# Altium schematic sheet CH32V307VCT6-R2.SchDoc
size A2
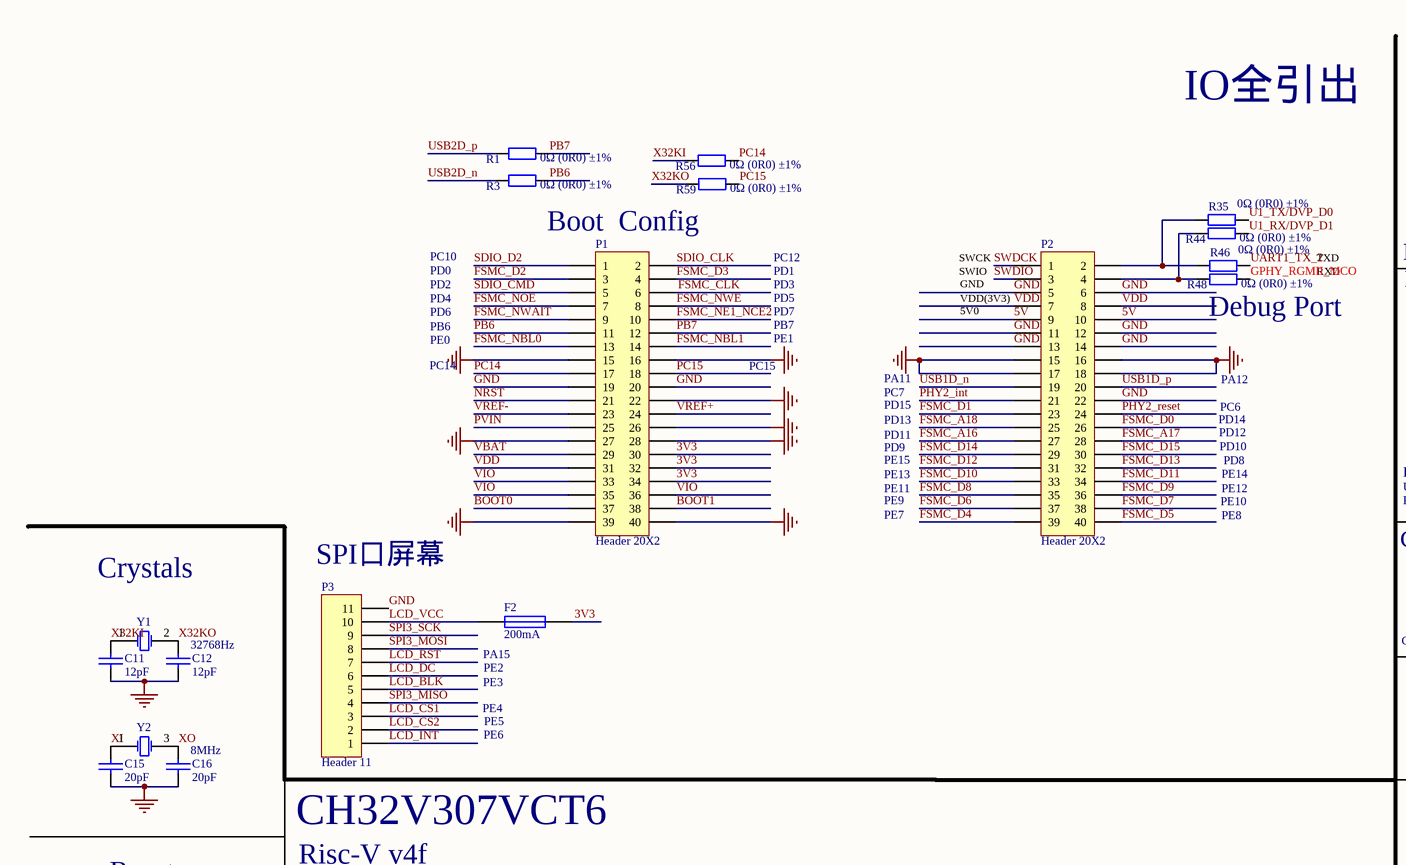
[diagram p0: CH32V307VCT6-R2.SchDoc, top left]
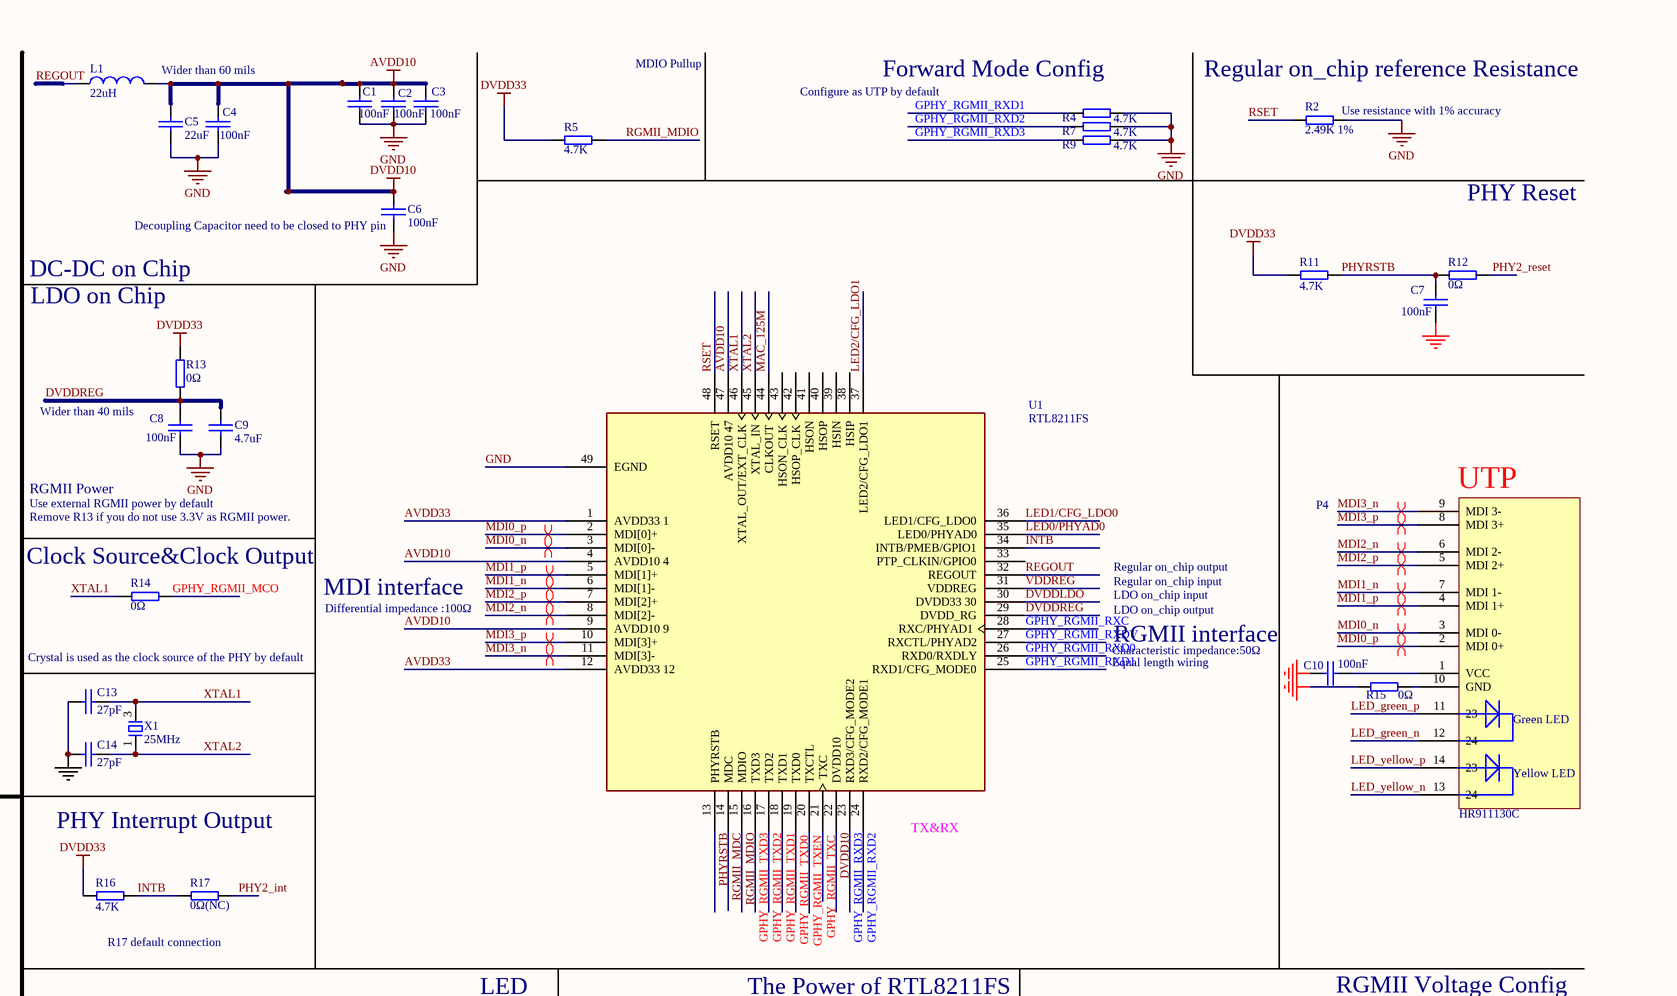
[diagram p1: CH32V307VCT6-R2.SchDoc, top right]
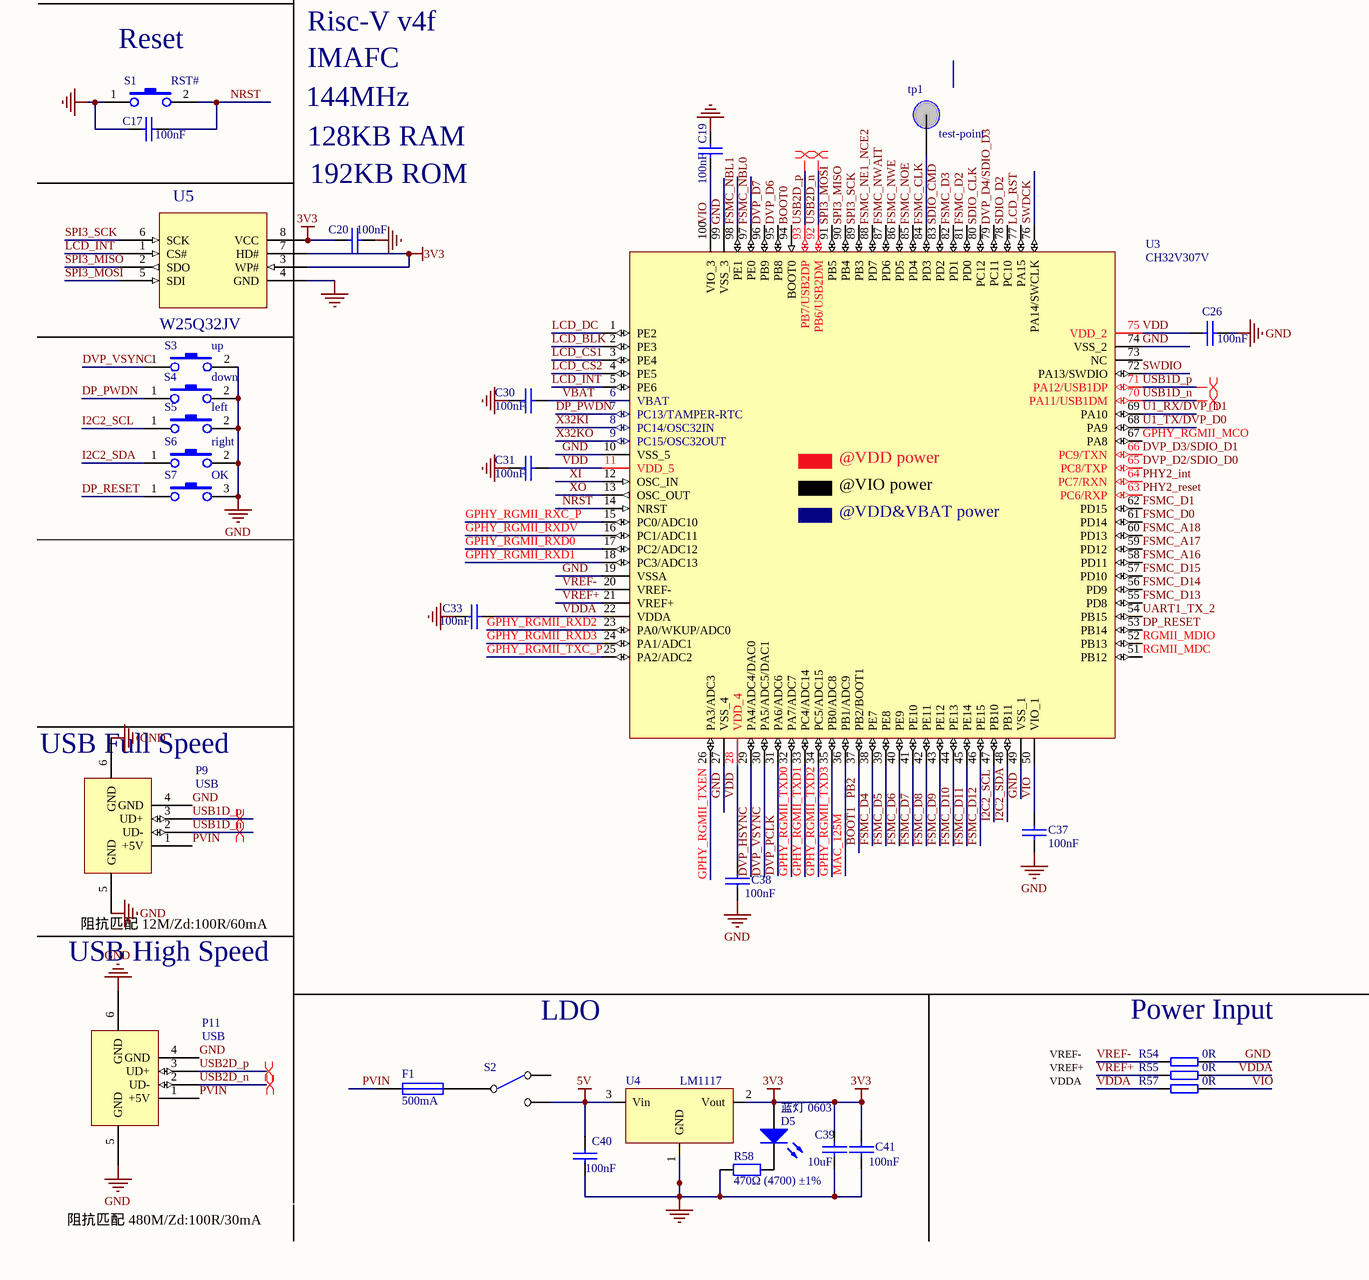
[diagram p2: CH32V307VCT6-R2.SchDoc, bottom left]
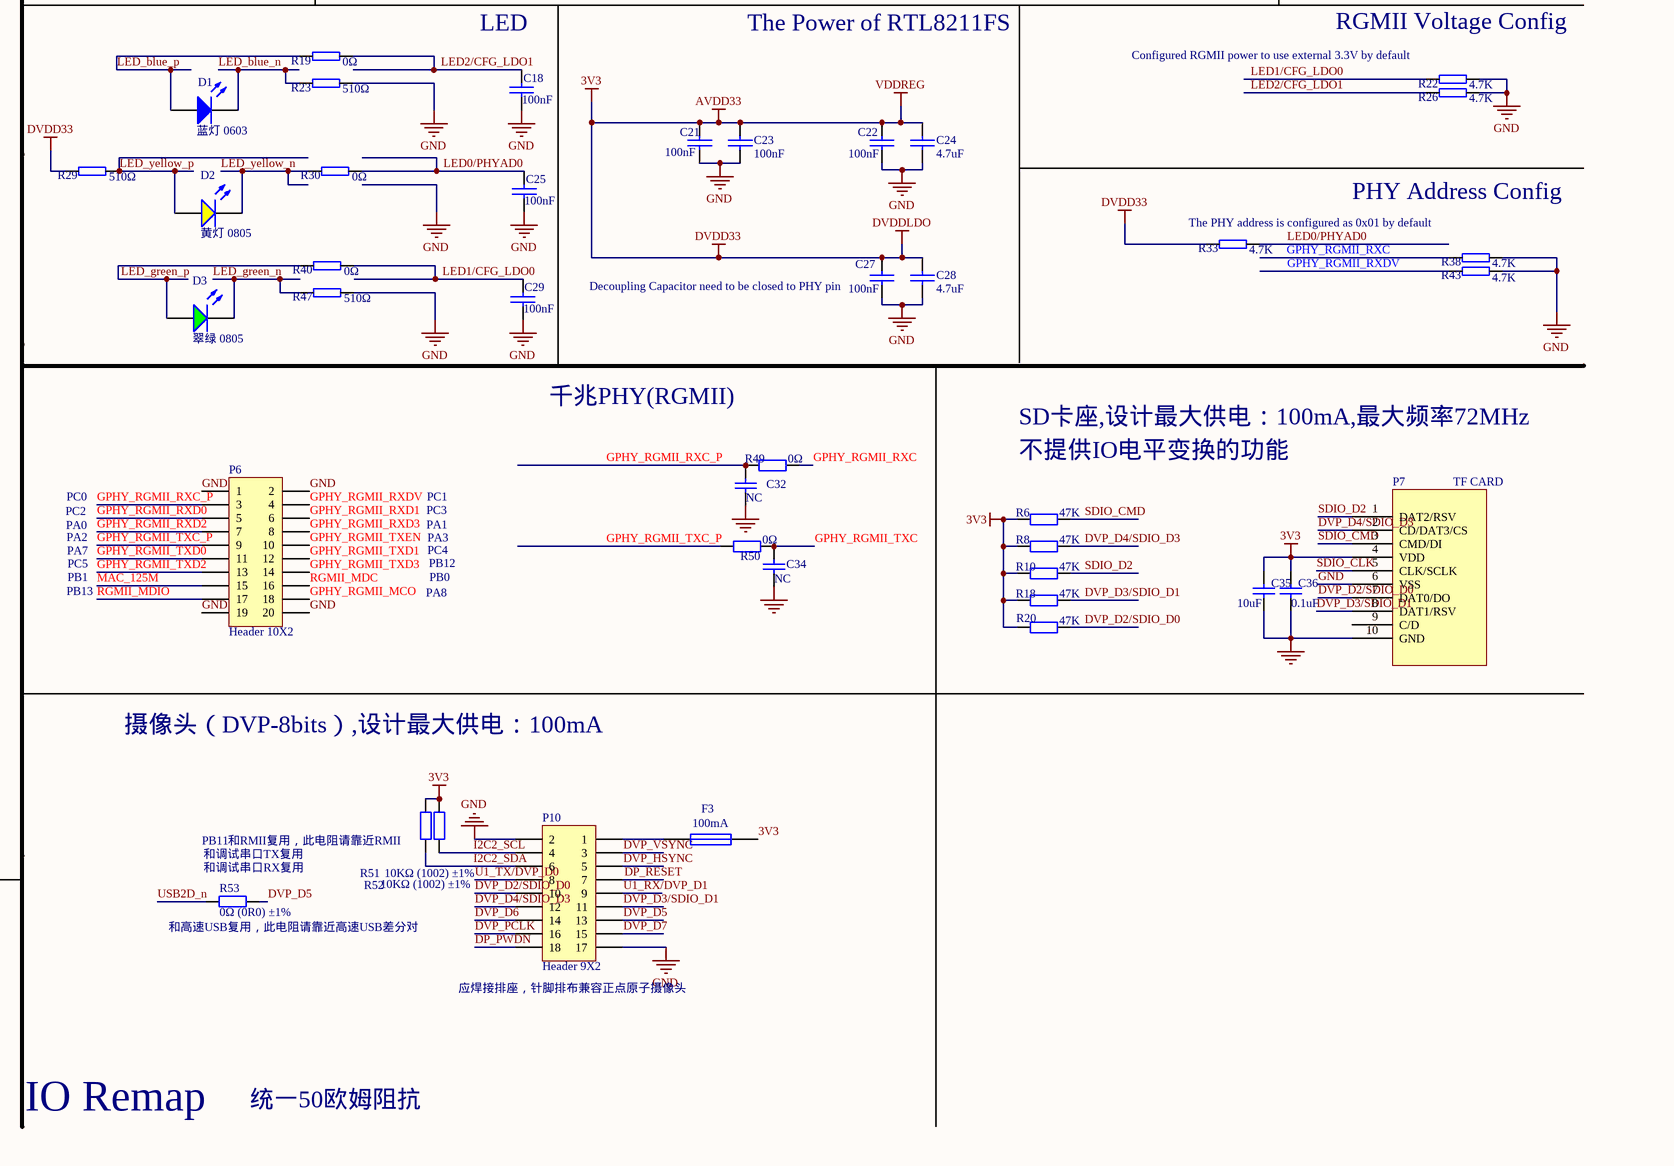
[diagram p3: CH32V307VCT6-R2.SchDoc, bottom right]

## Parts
C1  100nF  [0603_C]
C2  100nF  [0603_C]
C3  100nF  [0603_C]
C4  100nF  [0603_C]
C5  22uF  [0805_C]
C6  100nF  [0603_C]
C7  100nF  [0603_C]
C8  100nF  [0603_C]
C9  4.7uF  [0603_C]
C10  100nF  [0603_C]
C11  12pF  [0603_C]
C12  12pF  [0603_C]
C13  27pF  [0603_C]
C14  27pF  [0603_C]
C15  20pF  [0603_C]
C16  20pF  [0603_C]
C17  100nF  [0603_C]
C18  100nF  [0603_C]
C19  100nF  [0603_C]
C20  100nF  [0603_C]
C21  100nF  [0603_C]
C22  100nF  [0603_C]
C23  100nF  [0603_C]
C24  4.7uF  [0603_C]
C25  100nF  [0603_C]
C26  100nF  [0603_C]
C27  100nF  [0603_C]
C28  4.7uF  [0603_C]
C29  100nF  [0603_C]
C30  100nF  [0603_C]
C31  100nF  [0603_C]
C32  NC  [0402_C]
C33  100nF  [0603_C]
C34  NC  [0402_C]
C35  10uF  [0805_C]
C36  0.1uF  [0603_C]
C37  100nF  [0603_C]
C38  100nF  [0603_C]
C39  10uF  [0805_C]
C40  100nF  [0603_C]
C41  100nF  [0603_C]
D1  蓝灯 0603  [0603_LED_S1]
D2  黄灯 0805  [0603_LED_S1]
D3  翠绿 0805  [0603_LED_S1]
D5  蓝灯 0603  [0603_LED_S1]
F1  500mA  [0805]
F2  200mA  [0805]
F3  100mA  [0805]
L1  22uH  [0805]
P1  Header 20X2  [HDR2X20]
P2  Header 20X2  [HDR2X20]
P3  Header 11  [HDR1X11]
P4  HR911130C  [RJ45-1G]
P6  Header 10X2  [HDR2X10]
P7  TF CARD  [TF103]
P9  USB  [USBAF]
P10  Header 9X2  [HDR2X9]
P11  USB  [USBAF]
R1  0Ω (0R0) ±1%  [0402]
R2  2.49K 1%  [0603_R]
R3  0Ω (0R0) ±1%  [0402]
R4  4.7K  [0603_R]
R5  4.7K  [0603_R]
R6  47K  [0603_R]
R7  4.7K  [0603_R]
R8  47K  [0603_R]
R9  4.7K  [0603_R]
R10  47K  [0603_R]
R11  4.7K  [0603_R]
R12  0Ω  [0603_R]
R13  0Ω  [0603_R]
R14  0Ω  [0603_R]
R15  0Ω  [0603_R]
R16  4.7K  [0603_R]
R17  0Ω(NC)  [0603_R]
R18  47K  [0603_R]
R19  0Ω  [0603_R]
R20  47K  [0603_R]
R22  4.7K  [0603_R]
R23  510Ω  [0603_R]
R26  4.7K  [0603_R]
R29  510Ω  [0603_R]
R30  0Ω  [0603_R]
R33  4.7K  [0603_R]
R35  0Ω (0R0) ±1%  [0402_R]
R38  4.7K  [0603_R]
R40  0Ω  [0603_R]
R43  4.7K  [0603_R]
R44  0Ω (0R0) ±1%  [0402_R]
R46  0Ω (0R0) ±1%  [0402_R]
R47  510Ω  [0603_R]
R48  0Ω (0R0) ±1%  [0402_R]
R49  0Ω  [0402_R]
R50  0Ω  [0402_R]
R51  10KΩ (1002) ±1%  [0603_R]
R52  10KΩ (1002) ±1%  [0603_R]
R53  0Ω (0R0) ±1%  [0402]
R54  0R  [0402]
R55  0R  [0402]
R56  0Ω (0R0) ±1%  [0402]
R57  0R  [0402]
R58  470Ω (4700) ±1%  [0603_R]
R59  0Ω (0R0) ±1%  [0402]
S1  RST#  [SMD_6.1x3.65x2.5mm-KEY]
S2  SW SPDT  [Horizontal Slide Switch_8.7x4.4mm-2D]  (value not drawn)
S3  up  [SMD_6.1x3.65x2.5mm-KEY]
S4  down  [SMD_6.1x3.65x2.5mm-KEY]
S5  left  [SMD_6.1x3.65x2.5mm-KEY]
S6  right  [SMD_6.1x3.65x2.5mm-KEY]
S7  OK  [KEYD]
tp1  test-point  [POINT]
U1  RTL8211FS  [QFN-48_6x6x04P]
U3  CH32V307V  [LQFP100]
U4  LM1117  [SOT-223]
U5  W25Q32JV  [SOIC-8_208mil]
X1  25MHz  [SMD-3225_4P]
Y1  32768Hz  [FC-135]
Y2  8MHz  [SMD-3225_4P]

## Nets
3V3: C20.2 C21.2 C22.2 C23.2 C24.2 C27.2 C28.2 C35.2 C36.2 C39.1 C41.1 D5.A F2.2 F3.2 P1.30 P1.32 P1.34 P7.4(VDD) R5.1 R6.2 R8.2 R10.2 R11.2 R13.2 R16.2 R18.2 R20.2 R29.1 R33.1 R51.2 R52.2 U1.1(AVDD33_1) U1.12(AVDD33_12) U1.30(DVDD33_30) U1.31(VDDREG) U4.2(Vout) U5.3(WP#) U5.7(HD#) U5.8(VCC)  [also labelled AVDD33, DVDD33, DVDDLDO, VDDREG]
5V: C40.1 P2.9 P2.10 S2.2(NC) U4.3(Vin)
AVDD10: C1.2 C2.2 C3.2 C4.2 C5.2 C6.2 L1.2 U1.4(AVDD10_4) U1.9(AVDD10_9) U1.22(DVDD10) U1.47(AVDD10_47)  [also labelled DVDD10]
GND: C1.1 C2.1 C3.1 C4.1 C5.1 C6.1 C7.1 C8.1 C9.1 C10.2 C11.1 C12.1 C13.1 C14.1 C15.1 C16.1 C17.1 C18.2 C19.2 C20.1 C21.1 C22.1 C23.1 C24.1 C25.2 C26.1 C27.1 C28.1 C29.2 C30.1 C31.2 C32.1 C33.2 C34.1 C35.1 C36.1 C37.1 C38.1 C39.2 C40.2 C41.2 P1.15 P1.16 P1.19 P1.20 P1.22 P1.26 P1.27 P1.28 P1.39 P1.40 P2.5 P2.6 P2.11 P2.12 P2.13 P2.14 P2.15 P2.16 P2.17 P2.18 P2.22 P3.11 P6.1 P6.2 P6.19 P6.20 P7.6(VSS) P7.10(GND) P9.4(GND) P9.5(GND) P9.6(GND) P10.2 P10.17 P11.4(GND) P11.5(GND) P11.6(GND) R2.2 R4.2 R7.2 R9.2 R15.2 R22.2 R23.2 R26.2 R38.2 R43.2 R47.2 R54.1 R58.1 S1.1 S3.2 S4.2 S5.2 S6.2 S7.3 U1.49(EGND) U3.10(VSS_5) U3.19(VSSA) U3.27(VSS_4) U3.49(VSS_1) U3.74(VSS_2) U3.99(VSS_3) U4.1(GND) U5.4(GND)
BOOT0: P1.37 U3.94(BOOT0)
BOOT1: P1.38 U3.37(PB2/BOOT1)  [also labelled PB2]
DP_PWDN: P10.18 S4.1 U3.7(PC13/TAMPER-RTC)
DP_RESET: P10.7 S7.1 U3.53(PB14)
DVDDREG: C8.2 C9.2 R13.1 U1.29(DVDD_RG)
DVP_D2/SDIO_D0: P7.7(DAT0/DO) P10.10 R20.1 U3.65(PC8/TXP)
DVP_D3/SDIO_D1: P7.8(DAT1/RSV) P10.11 R18.1 U3.66(PC9/TXN)
DVP_D4/SDIO_D3: P7.2(CD/DAT3/CS) P10.12 R8.1 U3.79(PC11)
DVP_D5: P10.13 R53.2
DVP_D6: P10.14 U3.95(PB8)
DVP_D7: P10.15 U3.96(PB9)
DVP_HSYNC: P10.5 U3.29(PA4/ADC4/DAC0)
DVP_PCLK: P10.16 U3.31(PA6/ADC6)
DVP_VSYNC: P10.3 S3.1 U3.30(PA5/ADC5/DAC1)
FSMC_A16: P2.27 U3.58(PD11)
FSMC_A17: P2.28 U3.59(PD12)
FSMC_A18: P2.25 U3.60(PD13)
FSMC_CLK: P1.6 tp1.1(point) U3.84(PD3)
FSMC_D0: P2.26 U3.61(PD14)
FSMC_D1: P2.23 U3.62(PD15)
FSMC_D2: P1.3 U3.81(PD0)
FSMC_D3: P1.4 U3.82(PD1)
FSMC_D4: P2.39 U3.38(PE7)
FSMC_D5: P2.40 U3.39(PE8)
FSMC_D6: P2.37 U3.40(PE9)
FSMC_D7: P2.38 U3.41(PE10)
FSMC_D8: P2.35 U3.42(PE11)
FSMC_D9: P2.36 U3.43(PE12)
FSMC_D10: P2.33 U3.44(PE13)
FSMC_D11: P2.34 U3.45(PE14)
FSMC_D12: P2.31 U3.46(PE15)
FSMC_D13: P2.32 U3.55(PD8)
FSMC_D14: P2.29 U3.56(PD9)
FSMC_D15: P2.30 U3.57(PD10)
FSMC_NBL0: P1.13 U3.97(PE0)
FSMC_NBL1: P1.14 U3.98(PE1)
FSMC_NE1_NCE2: P1.10 U3.88(PD7)
FSMC_NOE: P1.7 U3.85(PD4)
FSMC_NWAIT: P1.9 U3.87(PD6)
FSMC_NWE: P1.8 U3.86(PD5)
GPHY_RGMII_MCO: P6.18 R14.2 R48.2 U3.67(PA8)
GPHY_RGMII_RXC: R38.1 R49.1 U1.28(RXC/PHYAD1)
GPHY_RGMII_RXC_P: C32.2 P6.3 R49.2 U3.15(PC0/ADC10)
GPHY_RGMII_RXD0: P6.5 U1.26(RXD0/RXDLY) U3.17(PC2/ADC12)
GPHY_RGMII_RXD1: P6.6 R4.1 U1.25(RXD1/CFG_MODE0) U3.18(PC3/ADC13)
GPHY_RGMII_RXD2: P6.7 R7.1 U1.24(RXD2/CFG_MODE1) U3.23(PA0/WKUP/ADC0)
GPHY_RGMII_RXD3: P6.8 R9.1 U1.23(RXD3/CFG_MODE2) U3.24(PA1/ADC1)
GPHY_RGMII_RXDV: P6.4 R43.1 U1.27(RXCTL/PHYAD2) U3.16(PC1/ADC11)
GPHY_RGMII_TXC: C34.2 R50.1 U1.21(TXC)
GPHY_RGMII_TXC_P: P6.9 R50.2 U3.25(PA2/ADC2)
GPHY_RGMII_TXD0: P6.11 U1.19(TXD0) U3.32(PA7/ADC7)
GPHY_RGMII_TXD1: P6.12 U1.18(TXD1) U3.33(PC4/ADC14)
GPHY_RGMII_TXD2: P6.13 U1.17(TXD2) U3.34(PC5/ADC15)
GPHY_RGMII_TXD3: P6.14 U1.16(TXD3) U3.35(PB0/ADC8)
GPHY_RGMII_TXEN: P6.10 U1.20(TXCTL) U3.26(PA3/ADC3)
I2C2_SCL: P10.4 R51.1 S5.1 U3.47(PB10)
I2C2_SDA: P10.6 R52.1 S6.1 U3.48(PB11)
INTB: R16.1 R17.1 U1.34(INTB/PMEB/GPIO1)
LCD_BLK: P3.5 U3.2(PE3)
LCD_CS1: P3.3 U3.3(PE4)
LCD_CS2: P3.2 U3.4(PE5)
LCD_DC: P3.6 U3.1(PE2)
LCD_INT: P3.1 U3.5(PE6) U5.1(CS#)
LCD_RST: P3.7 U3.77(PA15)
LCD_VCC: F2.1 P3.10
LED0/PHYAD0: C25.1 R30.2 R33.2 U1.35(LED0/PHYAD0)
LED1/CFG_LDO0: C29.1 R22.1 R40.2 U1.36(LED1/CFG_LDO0)
LED2/CFG_LDO1: C18.1 R19.2 R26.1 U1.37(LED2/CFG_LDO1)
LED_blue_n: D1.K R23.1
LED_blue_p: D1.A R19.1
LED_green_n: D3.K P4.12(24) R47.1
LED_green_p: D3.A P4.11(23) R40.1
LED_yellow_n: D2.K P4.13(24) R30.1
LED_yellow_p: D2.A P4.14(23) R29.2
MAC_125M: P6.15 U1.44(CLKOUT) U3.36(PB1/ADC9)
MDI0_n: P4.3(MDI_0-) U1.3(MDI[0]-)
MDI0_p: P4.2(MDI_0+) U1.2(MDI[0]+)
MDI1_n: P4.7(MDI_1-) U1.6(MDI[1]-)
MDI1_p: P4.4(MDI_1+) U1.5(MDI[1]+)
MDI2_n: P4.6(MDI_2-) U1.8(MDI[2]-)
MDI2_p: P4.5(MDI_2+) U1.7(MDI[2]+)
MDI3_n: P4.9(MDI_3-) U1.11(MDI[3]-)
MDI3_p: P4.8(MDI_3+) U1.10(MDI[3]+)
NRST: C17.2 P1.21 S1.2 U3.14(NRST)
PB6: P1.11 R3.2
PB7: P1.12 R1.2
PC14: P1.17 R56.2
PC15: P1.18 R59.2
PHY2_int: P2.21 R17.2 U3.64(PC7/RXN)
PHY2_reset: P2.24 R12.2 U3.63(PC6/RXP)
PHYRSTB: C7.2 R11.1 R12.1 U1.13(PHYRSTB)
PVIN: F1.1 P1.25 P9.1(+5V) P11.1(+5V)
REGOUT: L1.1 U1.32(REGOUT)
RGMII_MDC: P6.16 U1.14(MDC) U3.51(PB12)
RGMII_MDIO: P6.17 R5.2 U1.15(MDIO) U3.52(PB13)
RSET: R2.1 U1.48(RSET)
SDIO_CLK: P1.2 P7.5(CLK/SCLK) U3.80(PC12)
SDIO_CMD: P1.5 P7.3(CMD/DI) R6.1 U3.83(PD2)
SDIO_D2: P1.1 P7.1(DAT2/RSV) R10.1 U3.78(PC10)
SPI3_MISO: P3.4 U3.90(PB4) U5.2(SDO)
SPI3_MOSI: P3.8 U3.91(PB5) U5.5(SDI)
SPI3_SCK: P3.9 U3.89(PB3) U5.6(SCK)
SWDCK: P2.1 U3.76(PA14/SWCLK)
SWDIO: P2.3 U3.72(PA13/SWDIO)
U1_RX/DVP_D1: P10.9 R44.2 U3.69(PA10)
U1_TX/DVP_D0: P10.8 R35.2 U3.68(PA9)
UART1_TX_2: R46.2 U3.54(PB15)
USB1D_n: P2.19 P9.2(UD-) U3.70(PA11/USB1DM)
USB1D_p: P2.20 P9.3(UD+) U3.71(PA12/USB1DP)
USB2D_n: P11.2(UD-) R3.1 R53.1 U3.92(PB6/USB2DM)
USB2D_p: P11.3(UD+) R1.1 U3.93(PB7/USB2DP)
VBAT: C30.2 P1.29 U3.6(VBAT)
VDD: C26.2 C31.1 C38.2 P1.31 P2.7 P2.8 U3.11(VDD_5) U3.28(VDD_4) U3.75(VDD_2)
VDDA: C33.1 R55.1 R57.2 U3.22(VDDA)
VIO: C19.1 C37.2 P1.33 P1.35 P1.36 R57.1 U3.50(VIO_1) U3.100(VIO_3)
VREF+: P1.24 R55.2 U3.21(VREF+)
VREF-: P1.23 R54.2 U3.20(VREF-)
X32KI: C11.2 R56.1 U3.8(PC14/OSC32IN) Y1.1(OSC1)
X32KO: C12.2 R59.1 U3.9(PC15/OSC32OUT) Y1.2(OSC2)
XI: C15.2 U3.12(OSC_IN) Y2.1(OSC1)
XO: C16.2 U3.13(OSC_OUT) Y2.3(OSC2)
XTAL1: C13.2 R14.1 U1.46(XTAL_OUT/EXT_CLK) X1.3
XTAL2: C14.2 U1.45(XTAL_IN) X1.1
NetC10_1: C10.1 P4.1(VCC)
NetD5_K: D5.K R58.2
NetF1_2: F1.2 S2.1(COMMON)
NetF3_1: F3.1 P10.1
NetP2_2: P2.2 R35.1 R46.1
NetP2_4: P2.4 R44.1 R48.1
NetP4_10: P4.10(GND) R15.1

Not connected (* = marked no-connect by the designer): P7 9(C/D); S2 3(NO); U1 33(PTP_CLKIN/GPIO0) 38(HSIP) 39(HSIN) 40(HSOP) 41(HSON) 42(HSOP_CLK) 43(HSON_CLK); U3 73(NC)

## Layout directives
differential pair: MDI0_n, MDI0_p, MDI1_n, MDI1_p, MDI2_n, MDI2_p, MDI3_n, MDI3_p, USB1D_n, USB1D_p, USB2D_n, USB2D_p

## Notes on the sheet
- MDIO Pullup
- IO全引出
- (near L1) Wider than 60 mils
- Configure as UTP by default
- Forward Mode Config
- (near R2) Regular on_chip reference Resistance
- (near R2) Use resistance with 1% accuracy
- Boot  Config
- (near C6) Decoupling Capacitor need to be closed to PHY pin
- PHY Reset
- PC10
- PD2
- PD0
- PD4
- PD6
- PD7
- PD5
- PD3
- PD1
- PC12
- SWCK
- SWIO
- (near P2) VDD(3V3)
- 5V0
- GND
- (near R48) Debug Port
- TXD
- RXD
- DC-DC on Chip
- (near R13) LDO on Chip
- PC14
- PB6
- PE0
- PC15
- PE1
- PB7
- PA11
- PA12
- PC7
- PD15
- PD13
- PD11
- PD9
- PD14
- PD12
- PD10
- PC6
- Wider than 40 mils
- PE15
- PE13
- PE11
- PE9
- PE7
- PE10
- PE12
- PE14
- PE8
- PD8
- RGMII Power
- Use external RGMII power by default
- Remove R13 if you do not use 3.3V as RGMII power.
- (near P4) UTP
- Crystals
- (near P3) SPI口屏幕
- (near R14) Clock Source&Clock Output
- MDI interface
- Regular on_chip output
- Regular on_chip input
- LDO on_chip input
- (near F2) PA15
- Crystal is used as the clock source of the PHY by default
- Differential impedance :100Ω
- (near C10) Characteristic impedance:50Ω
- Equal length wiring
- (near C10) RGMII interface
- LDO on_chip output
- PE4
- PE3
- (near F2) PE2
- PE5
- PE6
- (near P3) CH32V307VCT6
- PHY Interrupt Output
- (near U1) TX&RX
- Reset
- Risc-V v4f
- IMAFC
- 144MHz
- 128KB RAM
- R17 default connection
- (near C18) LED
- The Power of RTL8211FS
- RGMII Voltage Config
- 192KB ROM
- (near R22) Configured RGMII power to use external 3.3V by default
- (near R33) The PHY address is configured as 0x01 by default
- PHY Address Config
- (near C27) Decoupling Capacitor need to be closed to PHY pin
- 千兆PHY(RGMII)
- SD卡座,设计最大供电：100mA,最大频率72MHz
- PC2
- PC0
- PC3
- PC1
- 不提供IO电平变换的功能
- PA0
- PA2
- PA7
- PB1
- PC5
- PA1
- PC4
- PA3
- PB12
- PB0
- (near P9) USB Full Speed
- PB13
- PA8
- 摄像头（DVP-8bits）,设计最大供电：100mA
- USB High Speed
- (near P9) 阻抗匹配 12M/Zd:100R/60mA
- (near R53) PB11和RMII复用，此电阻请靠近RMII
- (near R53) 和调试串口TX复用
- (near S2) LDO
- Power Input
- (near R53) 和调试串口RX复用
- VREF-
- VREF+
- VDDA
- (near R53) 和高速USB复用，此电阻请靠近高速USB差分对
- (near P10) 应焊接排座，针脚排布兼容正点原子摄像头
- 阻抗匹配 480M/Zd:100R/30mA
- IO Remap
- 统一50欧姆阻抗

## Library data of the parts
C1-C31 C33 C37-C41 = CAP: Capacitor
C32 C34 = 0603 2.7pF (2R7) 0.25pF 50V: 贴片电容
C35 C36 = Cap: Capacitor
D1 D5 = 0603 蓝灯: 发光二极管
D2 = 0805 黄灯: 发光二极管
D3 = 0805 翠绿: 发光二极管
F1-F3 = Fuse 1: Fuse
L1 = Inductor
P1 P2 = Header 20X2: Header, 20-Pin, Dual row
P3 = Header 11: Header, 11-Pin
P6 = Header 10X2: Header, 10-Pin, Dual row
P7 = TF_自弹
P9 P11 = USB: USB Port
P10 = Header 9X2: Header, 9-Pin, Dual row
R1 R3 R35 R44 R46 R48 R53 R56 R59 = 0402 0Ω (0R0) 1%: 贴片电阻
R2 R4 R5 R7 R9 R11-R17 R19 R22 R23 R26 R29 R30 R33 R38 R40 R43 R47 = Res
R6 R8 R10 R18 R20 R49 R50 = Res2: Resistor
R51 R52 = 0603 10KΩ (1002) 1%: 贴片电阻
R54 R55 R57 = R
R58 = 0603 470Ω (4700) 1%: 贴片电阻
S1 S3-S7 = KEY1
tp1 = test-point: 测试点
U1 = RTL8211FS(I): 千兆以太网物理层芯片; pin to pad: 49>0
U3 = CH32V307V: RISC-V FPU HD-MCU, 144MHz, USB_480M, USB OTG, 1000M Ethernet MAC, 2*CAN, FSMC+DVP
U4 = 6219P33M
U5 = Pro89C.tmp_25F512_2
X1 = XTAL-2P: 2脚无源脚晶振
Y1 Y2 = XTAL: Crystal Oscillator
